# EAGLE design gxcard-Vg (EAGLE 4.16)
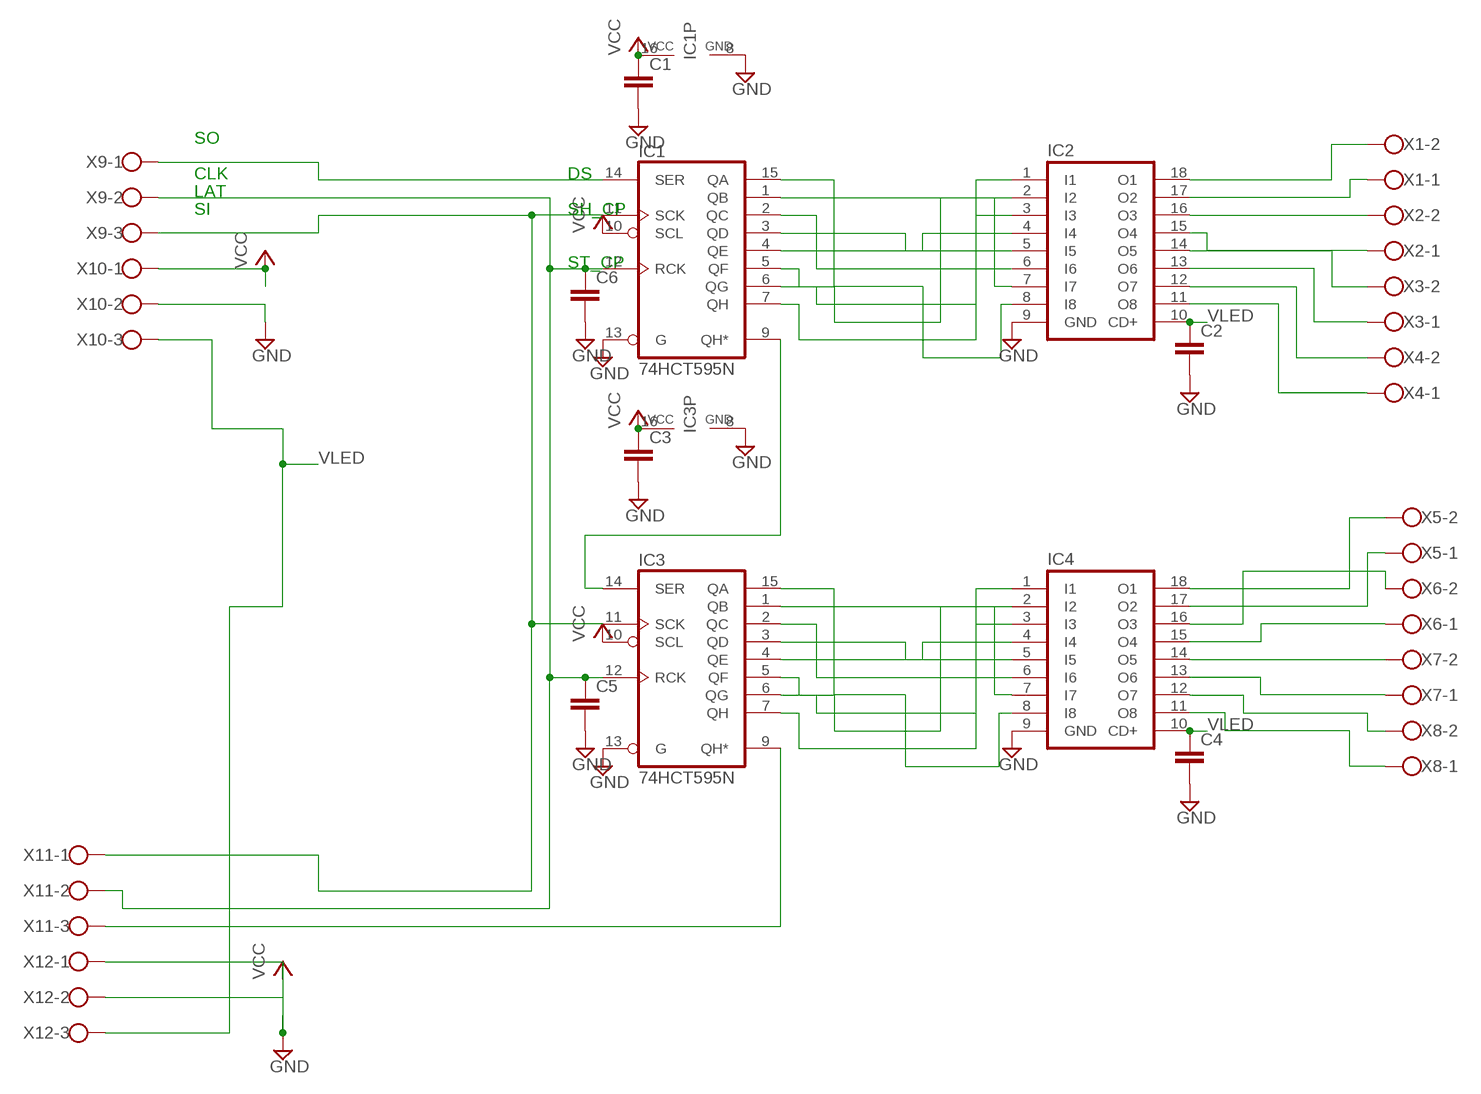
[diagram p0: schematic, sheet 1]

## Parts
C1  C-EU025-030X050  [C025-030X050]
C2  C-EU025-030X050  [C025-030X050]
C3  C-EU025-030X050  [C025-030X050]
C4  C-EU025-030X050  [C025-030X050]
C5  C-EU025-030X050  [C025-030X050]
C6  C-EU025-030X050  [C025-030X050]
IC1  74HCT595N  [DIL16]
IC2  ULN2803A  [DIL18]
IC3  74HCT595N  [DIL16]
IC4  ULN2803A  [DIL18]
X1  W237-102  [W237-102]
X2  W237-102  [W237-102]
X3  W237-102  [W237-102]
X4  W237-102  [W237-102]
X5  W237-102  [W237-102]
X6  W237-102  [W237-102]
X7  W237-102  [W237-102]
X8  W237-102  [W237-102]
X9  W237-103  [W237-103]
X10  W237-103  [W237-103]
X11  W237-103  [W237-103]
X12  W237-103  [W237-103]

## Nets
GND: C1.2 C2.2 C3.2 C4.2 C5.2 C6.2 IC1.8(GND) IC1.13(G) IC2.9(GND) IC3.8(GND) IC3.13(G) IC4.9(GND) X10.2 X12.2
N$1: IC1.14(SER) X9.1
N$2: IC3.9(QH*) X11.3
N$3: IC1.15(QA) IC2.8(I8)
N$4: IC1.1(QB) IC2.7(I7)
N$5: IC1.2(QC) IC2.6(I6)
N$6: IC1.3(QD) IC2.5(I5)
N$7: IC1.4(QE) IC2.4(I4)
N$8: IC1.5(QF) IC2.3(I3)
N$9: IC1.6(QG) IC2.2(I2)
N$10: IC1.7(QH) IC2.1(I1)
N$13: IC2.18(O1) X1.2
N$14: IC2.17(O2) X1.1
N$15: IC2.16(O3) X2.2
N$17: IC3.1(QB) IC4.7(I7)
N$18: IC3.15(QA) IC4.8(I8)
N$19: IC3.2(QC) IC4.6(I6)
N$20: IC3.3(QD) IC4.5(I5)
N$21: IC3.4(QE) IC4.4(I4)
N$22: IC3.5(QF) IC4.3(I3)
N$23: IC3.6(QG) IC4.2(I2)
N$24: IC3.7(QH) IC4.1(I1)
N$25: IC2.15(O4) X2.1
N$26: IC2.14(O5) X3.2
N$27: IC2.13(O6) X3.1
N$28: IC2.12(O7) X4.2
N$29: IC2.11(O8) X4.1
N$30: IC4.18(O1) X5.2
N$31: IC4.17(O2) X5.1
N$32: IC4.16(O3) X6.2
N$33: IC4.15(O4) X6.1
N$34: IC4.14(O5) X7.2
N$35: IC4.13(O6) X7.1
N$36: IC4.12(O7) X8.2
N$37: IC1.9(QH*) IC3.14(SER)
N$38: IC4.11(O8) X8.1
N$60: C5.1 C6.1 IC1.12(RCK) IC3.12(RCK) X9.2 X11.2
N$61: IC1.11(SCK) IC3.11(SCK) X9.3 X11.1
VCC: C1.1 C3.1 IC1.10(SCL) IC1.16(VCC) IC3.10(SCL) IC3.16(VCC) X10.1 X12.1
VLED: C2.1 C4.1 IC2.10(CD+) IC4.10(CD+) X10.3 X12.3

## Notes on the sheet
- SO
- CLK | DS
- LAT
- SI | SH_CP
- ST_CP

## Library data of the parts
C1-C6 = rcl:C-EU: CAPACITOR, European symbol
IC1 IC3 = 74xx-eu:74*595: 8-bit SHIFT REGISTER, output latch
IC2 IC4 = uln-udn:ULN2803A: DRIVER ARRAY
X1-X8 = con-wago-500:W237-102: WAGO SCREW CLAMP
X9-X12 = con-wago-500:W237-103: WAGO SCREW CLAMP

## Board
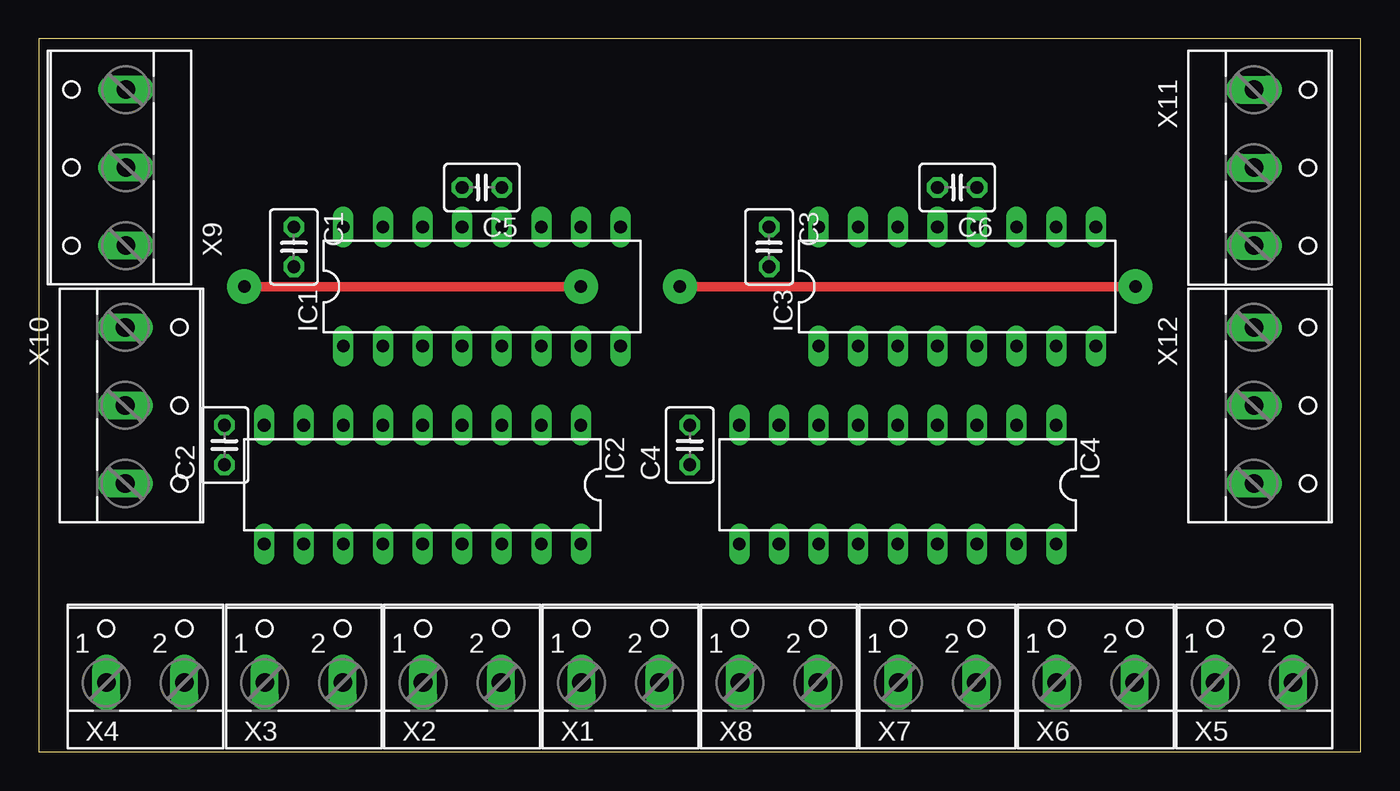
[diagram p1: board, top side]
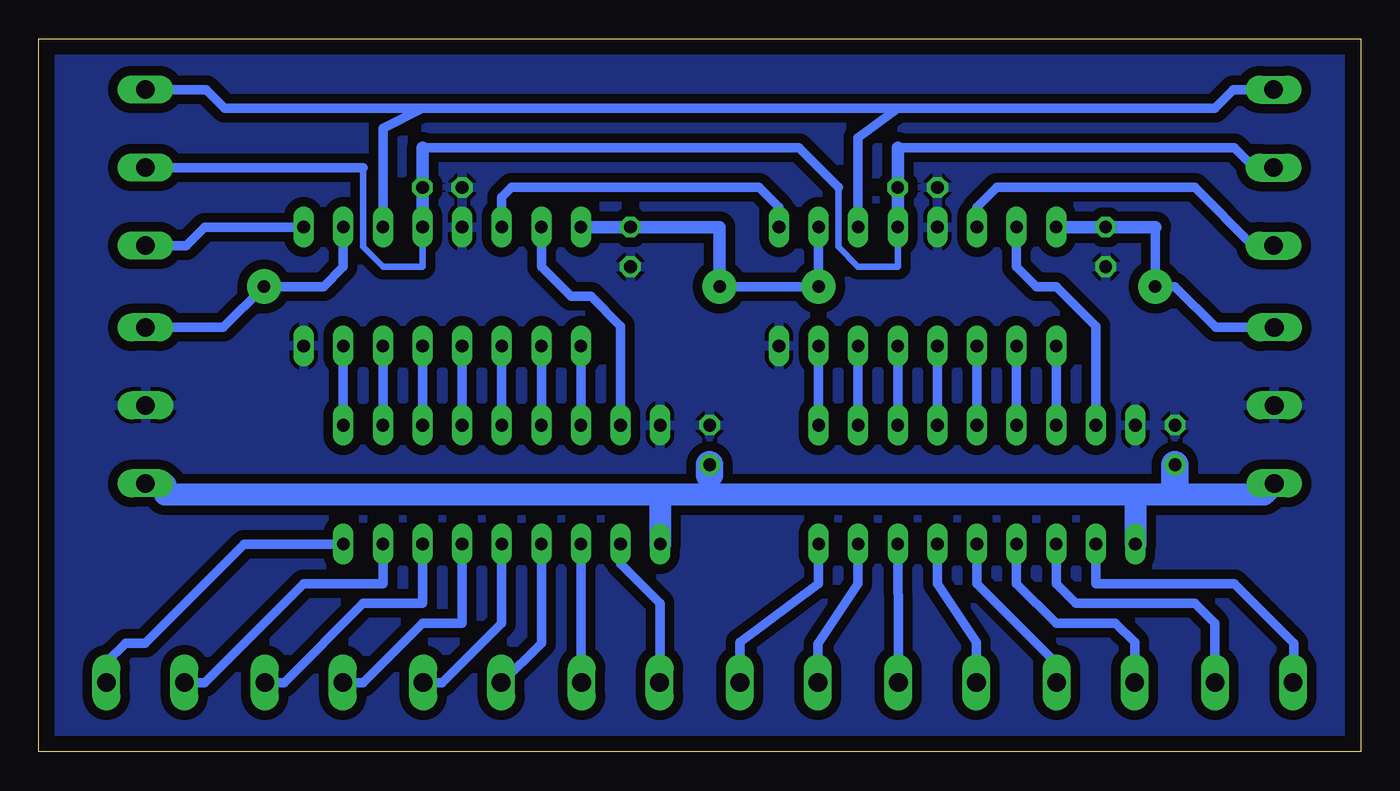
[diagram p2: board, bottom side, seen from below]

Size 84.76 x 45.71 mm. Coordinates in mm from the lower left corner, seen from the top.
Outline: 0,0 84.76,0 84.76,45.71 0,45.71 0,0
Copper layers (1*16): Top 0.035mm / dielectric 1.5mm / Bottom 0.035mm
Design rules "default": minimum track width 10mil, minimum drill 24mil, track to track 8mil, track to pad 8mil, pad to pad 8mil, via to via 8mil, smd to smd 8mil, copper to edge 40mil, drill to drill 8mil, minimum pad ring 10mil, minimum via ring 8mil, stop-mask expansion 4mil, vias tented up to drill 0mil, thermal gap 10mil

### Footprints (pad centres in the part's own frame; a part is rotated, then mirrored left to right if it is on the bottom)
C025-030X050 = drill 0.813 octagon: 1 -1.27,0; 2 1.27,0
DIL16 = drill 0.813 long: 1 -8.89,-3.81; 2 -6.35,-3.81; 3 -3.81,-3.81; 4 -1.27,-3.81; 5 1.27,-3.81; 6 3.81,-3.81; 7 6.35,-3.81; 8 8.89,-3.81; 9 8.89,3.81; 10 6.35,3.81; 11 3.81,3.81; 12 1.27,3.81; 13 -1.27,3.81; 14 -3.81,3.81; 15 -6.35,3.81; 16 -8.89,3.81
DIL18 = drill 0.813 long: 1 -10.16,-3.81; 2 -7.62,-3.81; 3 -5.08,-3.81; 4 -2.54,-3.81; 5 0,-3.81; 6 2.54,-3.81; 7 5.08,-3.81; 8 7.62,-3.81; 9 10.16,-3.81; 10 10.16,3.81; 11 7.62,3.81; 12 5.08,3.81; 13 2.54,3.81; 14 0,3.81; 15 -2.54,3.81; 16 -5.08,3.81; 17 -7.62,3.81; 18 -10.16,3.81
W237-102 = drill 1.194 long: 1 -2.5,-1.27; 2 2.5,-1.27
W237-103 = drill 1.194 long: 1 -5,-1.29; 2 0,-1.29; 3 5,-1.29

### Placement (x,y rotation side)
C1  16.34,32.38 270 top
C2  11.9,19.68 90 top
C3  46.83,32.38 270 top
C4  41.75,19.68 90 top
C5  28.41,36.19 180 top
C6  58.89,36.19 180 top
IC1  28.41,29.84 0 top
IC2  24.6,17.14 180 top
IC3  58.89,29.84 0 top
IC4  55.08,17.14 180 top
X1  37.3,5.71 0 top
X2  27.14,5.71 0 top
X3  16.98,5.71 0 top
X4  6.82,5.71 0 top
X5  77.94,5.71 0 top
X6  67.78,5.71 0 top
X7  57.62,5.71 0 top
X8  47.46,5.71 0 top
X9  4.28,37.46 90 top
X10  6.82,22.22 270 top
X11  79.21,37.46 270 top
X12  79.21,22.22 270 top

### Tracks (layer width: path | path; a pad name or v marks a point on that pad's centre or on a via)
GND
  pour Bottom (isolate 0.813): 0.47,45.08 84.29,45.08 84.29,0.63 0.47,0.63
  pour Bottom (isolate 0.61): 1.74,45.08 83.02,45.08 83.02,0.63 1.74,0.63
N$1
  Bottom 0.61: IC1.14 24.6,34.92 23.33,36.19 10.63,36.19 6.9,32.46 X9.1
N$2
  Bottom 0.61: IC3.9 74.13,33.65 75.32,32.46 X11.3
N$3
  Bottom 0.61: IC1.15 22.06,31.11 20.79,29.84 19.52,29.84 16.98,27.3 IC2.8
N$4
  Bottom 0.61: IC2.7 IC1.1
N$5
  Bottom 0.61: IC2.6 IC1.2
N$6
  Bottom 0.61: IC2.5 IC1.3
N$7
  Bottom 0.61: IC2.4 IC1.4
N$8
  Bottom 0.61: IC2.3 IC1.5
N$9
  Bottom 0.61: IC2.2 IC1.6
N$10
  Bottom 0.61: IC2.1 IC1.7
N$11
  pour Bottom (isolate 0.61): 0.47,45.08 84.29,45.08 84.29,0.63 0.47,0.63
N$13
  Bottom 0.61: X1.2 39.8,7.02 34.76,10.79 IC2.18
N$14
  Bottom 0.61: X1.1 34.8,6.94 32.22,10.79 IC2.17
N$15
  Bottom 0.61: X2.2 29.64,9.48 29.68,10.79 IC2.16
N$17
  Bottom 0.61: IC4.7 IC3.1
N$18
  Bottom 0.61: IC3.15 52.54,31.11 50.63,29.2 49.37,29.2 47.46,27.3 IC4.8
N$19
  Bottom 0.61: IC4.6 IC3.2
N$20
  Bottom 0.61: IC4.5 IC3.3
N$21
  Bottom 0.61: IC4.4 IC3.4
N$22
  Bottom 0.61: IC4.3 IC3.5
N$23
  Bottom 0.61: IC4.2 IC3.6
N$24
  Bottom 0.61: IC4.1 IC3.7
N$25
  Bottom 0.61: X2.1 24.64,7.02 27.14,10.79 IC2.15
N$26
  Bottom 0.61: X3.2 19.48,5.67 24.6,10.79 IC2.14
N$27
  Bottom 0.61: X3.1 14.48,7.02 15.71,8.25 19.52,8.25 22.06,10.79 IC2.13
N$28
  Bottom 0.61: IC2.12 19.52,10.79 18.25,9.52 10.63,9.52 9.36,8.25 9.36,4.44 X4.2
N$29
  Bottom 0.61: IC2.11 16.98,10.79 8.09,10.79 4.28,6.98 4.28,4.44 X4.1
N$30
  Bottom 0.61: X5.2 80.48,4.44 80.48,5.71 79.21,6.98 77.94,6.98 71.59,13.33 IC4.18
N$31
  Bottom 0.61: IC4.17 62.7,10.79 67.78,10.79 74.13,4.44 X5.1
N$32
  Bottom 0.61: IC4.16 60.16,9.52 63.97,9.52 69.05,4.44 X6.2 70.32,4.44
N$33
  Bottom 0.61: IC4.15 57.62,8.25 60.16,8.25 63.97,4.44 X6.1
N$34
  Bottom 0.61: X7.2 58.89,4.44 55.08,8.25 IC4.14
N$35
  Bottom 0.61: X7.1 55.08,4.44 52.54,6.98 IC4.13
N$36
  Bottom 0.61: X8.2 50,4.44 IC4.12
N$37
  Bottom 0.61: IC3.14 55.08,35.56 54.45,36.19 38.57,36.19 37.3,34.92 IC1.9
N$38
  Bottom 0.61: X8.1 44.92,4.44 44.92,9.52 47.46,12.06 IC4.11
N$60
  Bottom 0.406: 63.97,37.46 63.97,32.38 62.7,31.11 60.16,31.11 IC3.12 | 33.49,36.19 33.49,32.38 32.22,31.11 29.68,31.11 IC1.12
  Bottom 0.61: 29.68,38.73 8.09,38.73 6.82,37.46 X9.2 | 60.16,38.73 36.03,38.73 33.49,36.19 | 63.97,37.46 X11.2
  Bottom 0.813: 29.68,38.73 C5.1 IC1.12 | 60.16,38.73 C6.1 IC3.12
N$61
  Bottom 0.61: IC1.11 32.22,39.37 29.68,41.27 | 29.68,41.27 9.36,41.27 8.17,42.46 X9.3 | 29.68,41.27 60.16,41.27 | 60.16,41.27 72.86,41.27 74.05,42.46 X11.1 | IC3.11 62.7,40 60.16,41.27
VCC  (via drill 0.8 pad 2.18)
  Top 0.61: v13.17,29.84 v34.76,29.84 | v41.11,29.84 v70.32,29.84
  Bottom 0.61: v34.76,29.84 IC1.10 v34.76,29.84 | v34.76,29.84 v41.11,29.84 | 46.19,33.65 C3.1 | 16.98,33.65 C1.1 15.71,33.65 | 13.17,33.65 v13.17,29.84 11.9,29.84 9.28,27.22 X10.1 | X12.1 72.94,27.22 v70.32,29.84 66.51,29.84 65.24,31.11 IC3.10
  Bottom 0.813: v41.11,29.84 41.11,33.65 46.19,33.65 IC3.16 | 13.17,33.65 16.98,33.65 IC1.16
VLED
  Bottom 1.422: 41.75,16.5 41.75,17.77 | 41.75,16.5 44.92,16.5 | 44.92,16.5 IC4.10 | X12.3 76.65,17.16 76.67,16.5 44.92,16.5 | 14.44,16.5 41.75,16.5 | 14.44,16.5 IC2.10 | X10.3 5.53,17.16 6.19,16.5 11.9,16.5 | 11.9,16.5 14.44,16.5 | 11.9,16.5 11.9,17.22
  Bottom 1.778: 11.9,17.22 C2.1 | 41.75,17.77 C4.1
